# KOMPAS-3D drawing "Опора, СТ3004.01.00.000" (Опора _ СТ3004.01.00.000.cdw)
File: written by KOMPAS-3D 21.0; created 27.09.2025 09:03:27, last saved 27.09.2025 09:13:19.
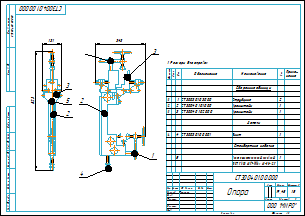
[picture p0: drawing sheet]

Sheet 1: A3, landscape

Document properties: Масса: 19.478308

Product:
- Part/product: Опора  | designation СТ3004.01.00.000
    Масса: 19.478308
    Форматы листов документа: A3
  - Component [standard]: Винт с шестигранной головкой ГОСТ Р ИСО 4017-М16 x 45-5.8-A2P  | pos. 5  | Материал: Сталь (density 1000 kg/m3); Масса: 0.01392; Раздел спецификации: Стандартные изделия; Рассекать на разрезах: no; additional columns: ГОСТ Р ИСО 4017-2013; М16 x 45 - 5.8 - A2P
  - Component [assembly]: Струбцина  | designation СТ3003.01.03.000-02  | pos. 1  | Масса: 1.075052; Форматы листов документа: A3; source file: ..\..\..\Стапель _ СТ3003.00.00.000\Опора _ СТ3003.01.00.000\2D\Струбцина _ СТ3003.01.03.000\Струбцина _ СТ3003.01.03.000.cdw, ..\..\..\Стапель _ СТ3003.00.00.000\Опора _ СТ3003.01.00.000\3D\Струбцина _ СТ3003.01.03.000\Струбцина _ СТ3003.01.03.000.a3d
  - Component [assembly]: Струбцина  | designation СТ3003.01.03.000  | pos. 1  | Масса: 1.103282; Раздел спецификации: Сборочные единицы; Форматы листов документа: A3; source file: ..\..\..\Стапель _ СТ3003.00.00.000\Опора _ СТ3003.01.00.000\2D\Струбцина _ СТ3003.01.03.000\Струбцина _ СТ3003.01.03.000.cdw, ..\..\..\Стапель _ СТ3003.00.00.000\Опора _ СТ3003.01.00.000\3D\Струбцина _ СТ3003.01.03.000\Струбцина _ СТ3003.01.03.000.a3d
  - Component [assembly]: Кронштейн  | designation СТ3004.01.02.000  | pos. 3  | Масса: 5.184451; Форматы листов документа: A3; source file: ..\3D\Кронштейн _ СТ3004.01.02.000\Кронштейн _ СТ3004.01.02.000.a3d, Кронштейн _ СТ3004.01.02.000\Кронштейн _ СТ3004.01.02.000.cdw
  - Component [assembly]: Кронштейн  | designation СТ3004.01.01.000  | pos. 2  | Масса: 11.762936; Форматы листов документа: A2; source file: ..\3D\Кронштейн _ СТ3004.01.01.000\Кронштейн _ СТ3004.01.01.000.a3d, Кронштейн _ СТ3004.01.01.000\Кронштейн _ СТ3004.01.01.000.cdw
  - Component [detail]: Винт  | designation СТ3003.01.00.001  | pos. 4  | Материал: Круг$d30 ГОСТ 2590-2006;Ст3сп ГОСТ 535-2005$ (density 7850 kg/m3); Масса: 0.303608; Форматы листов документа: A4; additional columns: 120; source file: ..\..\..\Стапель _ СТ3003.00.00.000\Опора _ СТ3003.01.00.000\2D\Винт _ СТ3003.01.00.001.cdw, ..\..\..\Стапель _ СТ3003.00.00.000\Опора _ СТ3003.01.00.000\3D\Винт _ СТ3003.01.00.001.m3d

Title block, sheet 1: Наименование: Опора; designation: СТ3004.01.00.000; Масса: 19,48; Количество листов документа: 1; organisation: ООО "МИРО"; Форматы листов документа: A3; stored path: C:\Users\Lutik\Yandex.Disk\Документы\Новая папка\Стапель №2\Стапель _ СТ3004.00.00.000\Опора _ СТ3004.01.00.000\2D\Опора _ СТ3004.01.00.000.cdw; Разработал: Тимонин

Referenced files in C:\Users\Lutik\Yandex.Disk\Документы\Новая папка\Стапель №2\Стапель _ СТ3003.00.00.000\Опора _ СТ3003.01.00.000\3D\Струбцина _ СТ3003.01.03.000\: Струбцина _ СТ3003.01.03.000.a3d, Опора _ СТ3003.01.03.001.m3d, Ось _ СТ3003.01.03.002.m3d
Referenced files in C:\Users\Lutik\Yandex.Disk\Документы\Новая папка\Стапель №2\Стапель _ СТ3003.00.00.000\Опора _ СТ3003.01.00.000\2D\Струбцина _ СТ3003.01.03.000\: Струбцина _ СТ3003.01.03.000.cdw
Referenced files in C:\Users\Lutik\Yandex.Disk\Документы\Новая папка\Стапель №2\Стапель _ СТ3004.00.00.000\Опора _ СТ3004.01.00.000\3D\Кронштейн _ СТ3004.01.02.000\: Кронштейн _ СТ3004.01.02.000.a3d, Направляющая _ СТ3004.01.02.001.m3d, Упор _ СТ3004.01.02.002.m3d
Referenced files in C:\Users\Lutik\Yandex.Disk\Документы\Новая папка\Стапель №2\Стапель _ СТ3004.00.00.000\Опора _ СТ3004.01.00.000\2D\Кронштейн _ СТ3004.01.02.000\: Кронштейн _ СТ3004.01.02.000.cdw
Referenced files in C:\Users\Lutik\Yandex.Disk\Документы\Новая папка\Стапель №2\Стапель _ СТ3003.00.00.000\Опора _ СТ3003.01.00.000\3D\: Винт _ СТ3003.01.00.001.m3d
Referenced files in C:\Users\Lutik\Yandex.Disk\Документы\Новая папка\Стапель №2\Стапель _ СТ3003.00.00.000\Опора _ СТ3003.01.00.000\2D\: Винт _ СТ3003.01.00.001.cdw
Referenced files in C:\Users\Lutik\Yandex.Disk\Документы\Новая папка\Стапель №2\Стапель _ СТ3004.00.00.000\Опора _ СТ3004.01.00.000\3D\Кронштейн _ СТ3004.01.01.000\: Кронштейн _ СТ3004.01.01.000.a3d, Упор _ СТ3004.01.01.001.m3d
Referenced files in C:\Users\Lutik\Yandex.Disk\Документы\Новая папка\Стапель №2\Стапель _ СТ3004.00.00.000\Опора _ СТ3004.01.00.000\2D\Кронштейн _ СТ3004.01.01.000\: Кронштейн _ СТ3004.01.01.000.cdw
Referenced files in C:\Users\Lutik\Yandex.Disk\Документы\Новая папка\Стапель №2\Стапель _ СТ3004.00.00.000\Опора _ СТ3004.01.00.000\3D\Кронштейн _ СТ3004.01.01.000\Основание _ СТ3004.01.01.100\: Пластина _ СТ3004.01.01.101.m3d, Основание _ СТ3004.01.01.100.a3d
Referenced files in C:\Users\Lutik\Yandex.Disk\Документы\Новая папка\Стапель №2\Стапель _ СТ3003.00.00.000\Опора _ СТ3003.01.00.000\3D\Кронштейн _ СТ3003.01.01.000\Основание _ СТ3003.01.01.100\: Пластина _ СТ3003.01.01.102.m3d
Referenced files in C:\Users\Lutik\Yandex.Disk\Документы\Новая папка\Стапель №2\Стапель _ СТ3003.00.00.000\Опора _ СТ3003.01.00.000\3D\Кронштейн _ СТ3003.01.01.000\: Направляющая _ СТ3003.01.01.003.m3d, Косынка _ СТ3003.01.01.002.m3d, Пластина _ СТ3003.01.01.006.m3d, Планка _ СТ3003.01.01.005.m3d, Опора _ СТ3003.01.01.004.m3d, Винт _ СТ3003.01.01.001.m3d
Referenced files in C:\Program Files\ASCON\KOMPAS-3D v21\Libs\PARTLib\DATA\vault\Methods\Kompas\3D\: PLib_Washer_1_712.m3d, PLib_Nut_ISO_1100.m3d, PLib_Bolt_1_ISO_1100.m3d
Referenced files in C:\Program Files\ASCON\KOMPAS-3D v21\Libs\PartLib\DATA\VAULT\Methods\Kompas\3D\: PLib_Screw_GOST_11738_1500.m3d, PLib_Piata_GOST_13437-68_813.m3d, PLib_Pin_3128_712.m3d, PLib_Bolt_1_900.m3d
Referenced files in C:\Users\Lutik\Yandex.Disk\Документы\Новая папка\Стапель №2\Стапель _ СТ3003.00.00.000\Опора _ СТ3003.01.00.000\3D\Кронштейн _ СТ3003.01.02.000\: Пластина _ СТ3003.01.02.002.m3d
Referenced files in C:\Program Files\ASCON\KOMPAS-3D v21\Libs\PARTLib\DATA\vault\Methods\Kompas\3D\Holding_devices\13447_13430_13431_13426_8921\: PLib_Pin_GOST_3128-70_813.m3d, Plib_Screw_GOST_13433_13435_813.m3d, Plib_Screw_GOST_13431-68_813.a3d
Referenced files: PLib_Hand_lever_GOST_13447-68_813.a3d
Referenced files in C:\Users\Lutik\Yandex.Disk\Документы\Новая папка\Стапель №2\Стапель _ СТ3004.00.00.000\Опора _ СТ3004.01.00.000\3D\: Опора _ СТ3004.01.00.000.a3d
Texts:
  Винт с шестигранной головкой ГОСТ Р ИСО 4017-М16 x 45-5.8-A2P
  Винт с шестигранной головкой
  ГОСТ Р ИСО
  СТ3003.01.03.000
  Струбцина
  СТ3004.01.02.000
  Кронштейн
  СТ3003.01.00.001
  Винт
  СТ3004.01.01.000
  СТ3003.01.03.000 - 02
  СТ3003.01.03.000 - 02
  СТ3003.01.03.000-02
  ГОСТ Р ИСО 4017-М16 x 45-5.8-A2P
  СТ3004.00.00.000
  Пластина
  СТ3004.01.01.101
  СТ3004.01.01.101 Пластина
  СТ3003.01.01.102
  СТ3003.01.01.102 Пластина
  Основание
  СТ3004.01.01.100
  СТ3004.01.01.100 Основание
  Направляющая
  СТ3003.01.01.003
  СТ3003.01.01.003 Направляющая
  Косынка
  СТ3003.01.01.002
  СТ3003.01.01.002 Косынка
  СТ3003.01.01.006
  СТ3003.01.01.006 Пластина
  Планка
  СТ3003.01.01.005
  СТ3003.01.01.005 Планка
  СТ3003.01.01.004
  СТ3003.01.01.004 Опора
  СТ3003.01.01.001
  СТ3003.01.01.001 Винт
  Упор
  СТ3004.01.01.001
  СТ3004.01.01.001 Упор
  Шайба A.8.01.10.019 ГОСТ 11371-78
  Винт М8-6gx25.56.019 ГОСТ 11738-84
  Винт М6-6gx20.56.019 ГОСТ 11738-84
  Гайка шестигранная низкая ГОСТ ISO 4035-М12-05-A2P
  СТ3004.01.01.000 Кронштейн
  СТ3004.01.02.001
  СТ3004.01.02.001 Направляющая
  СТ3004.01.02.002
  СТ3004.01.02.002 Упор
  СТ3003.01.02.002
  СТ3003.01.02.002 Пластина
  Винт М8-6gx35.56.019 ГОСТ 11738-84
  СТ3004.01.02.000 Кронштейн
  СТ3003.01.00.001 Винт
  СТ3003.01.03.001
  СТ3003.01.03.001 Опора
  Ось
  СТ3003.01.03.002
  СТ3003.01.03.002 Ось
  ГОСТ 3128-70 Штифты цилиндрические
  ГОСТ 13429-68 Винты нажимные с концом под пяту
  Винт 7006-0537 ГОСТ 13431-68
  Пята 7007-0035 ГОСТ 13437-68
  Штифт 4x16 ГОСТ 3128-70
  Шайба A 6.01.10.019 ГОСТ 6958-78
  Винт с шестигранной головкой ГОСТ Р ИСО 4017-М6 x 25-5.8-A2P
  СТ3003.01.03.000 Струбцина
  Болт М6-6gx25.58.019 ГОСТ 7798-70
  СТ3003.01.03.000-02 Струбцина
  СТ3004.01.00.000 Опора
Dimensions and other numbers on the sheet: 5.8; 1; 2; 5; 3; 4; 1:5; 19,48; 02

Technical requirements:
  Размеры для справок.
